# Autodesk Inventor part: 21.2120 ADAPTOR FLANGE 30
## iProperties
Created: 2012-10
Part Number: 21.2120 ADAPTOR FLANGE 30
Document SubType Name: Modeling
Designer: Administrator
Density: 7.85 g/cm^3
Material: Steel
Mass: 235.848 g
Surface Area: 153.741 cm^2
Volume: 30.0443 cm^3
Translation Standard: STEP AP214IS
FileName: 21-2120-0.stp
PreProcessor: Mechanical Desktop 2011
PostProcessor: Build: 236a, Release: 2009 RTM - Date: Fri 02/22/2008
Sent Units: MM
Uncertainty: 1.0000000000000002e-06
Author: Administrator
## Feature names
1. Base1
